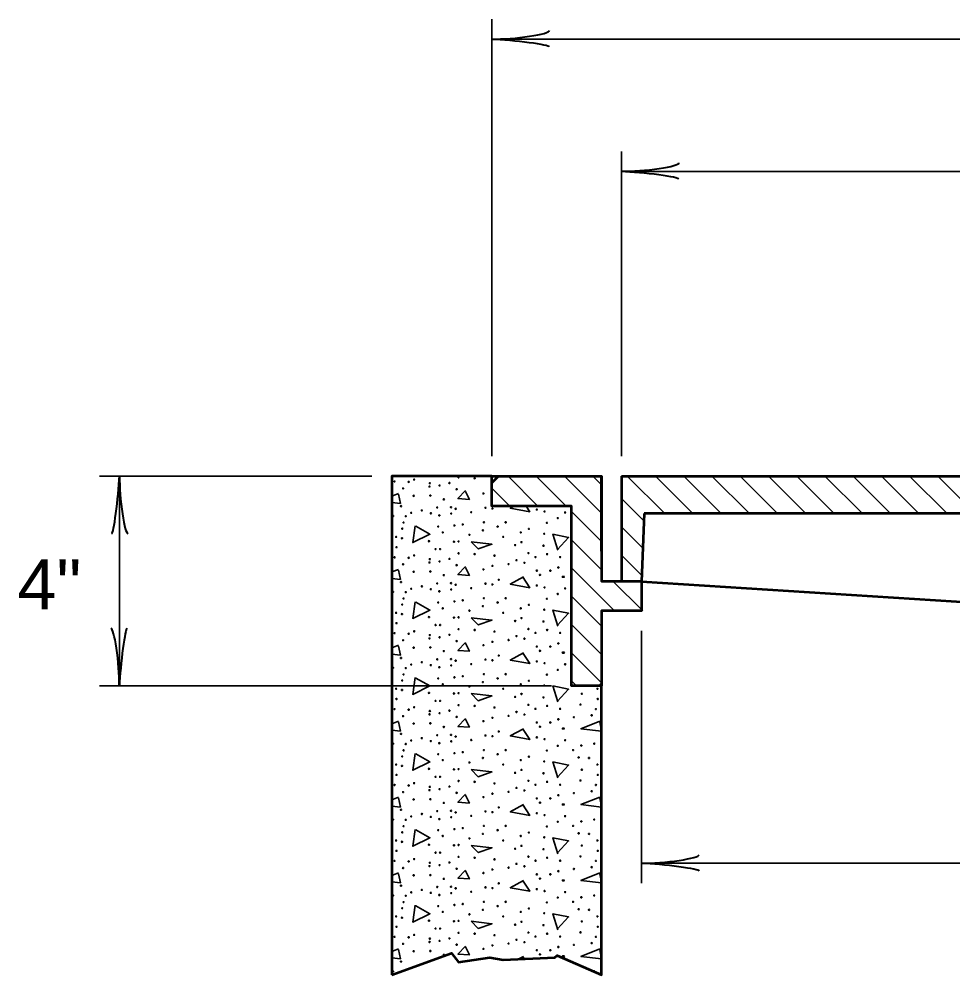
# Model space of a CAD drawing. Extents: x 788 to 1469, y -1 to 439.
# Drawn here: x 1096.98 to 1143.75, y 217.38 to 265.23 of the extents above; entities that cross this region are included whole.
import ezdxf

# ---------------------------------------------------------------- set-up
doc = ezdxf.new("R2010")
doc.units = 0
doc.layers.add('1', color=7, linetype='Continuous', lineweight=35)

msp = doc.modelspace()

# ---------------------------------------------------------------- linework, layer by layer
at = {"layer": '1'}
for p, q in [((1120.652, 243.348), (1120.652, 265.229)), ((1120.652, 264.229), (1184.152, 264.229)), ((1127.152, 243.348), (1127.152, 258.601)), ((1127.152, 257.601), (1177.652, 257.601)), ((1114.652, 242.348), (1101.003, 242.348)), ((1102.003, 242.348), (1102.003, 231.848)), ((1122.968, 240.848), (1121.468, 242.348)), ((1124.382, 240.848), (1122.882, 242.348)), ((1126.152, 240.493), (1124.297, 242.348)), ((1126.152, 241.907), (1125.711, 242.348)), ((1127.439, 242.348), (1129.314, 240.473)), ((1128.854, 242.348), (1130.729, 240.473)), ((1130.268, 242.348), (1132.143, 240.473)), ((1131.682, 242.348), (1133.557, 240.473)), ((1133.096, 242.348), (1134.971, 240.473)), ((1134.51, 242.348), (1136.385, 240.473)), ((1135.925, 242.348), (1137.8, 240.473)), ((1137.339, 242.348), (1139.214, 240.473)), ((1138.753, 242.348), (1140.628, 240.473)), ((1140.167, 242.348), (1142.042, 240.473)), ((1141.582, 242.348), (1143.457, 240.473)), ((1142.996, 242.348), (1144.871, 240.473)), ((1121.554, 240.848), (1120.652, 241.75)), ((1115.977, 241.482), (1115.652, 241.35)), ((1127.152, 241.221), (1128.267, 240.106)), ((1126.152, 239.079), (1124.652, 240.579)), ((1127.152, 239.807), (1128.215, 238.744)), ((1126.152, 237.664), (1124.652, 239.164)), ((1127.152, 238.393), (1128.163, 237.382)), ((1115.977, 237.682), (1115.652, 237.55)), ((1126.804, 235.598), (1124.652, 237.75)), ((1128.218, 235.598), (1126.718, 237.098)), ((1126.152, 234.836), (1124.652, 236.336)), ((1126.152, 233.422), (1124.652, 234.922)), ((1128.152, 234.598), (1128.152, 221.972)), ((1115.977, 233.882), (1115.652, 233.75)), ((1126.152, 232.007), (1124.652, 233.507)), ((1124.897, 231.848), (1124.652, 232.093)), ((1123.652, 231.848), (1101.003, 231.848)), ((1115.977, 230.082), (1115.652, 229.951)), ((1126.152, 229.605), (1126.057, 230.042)), ((1115.977, 226.282), (1115.652, 226.15)), ((1126.152, 225.805), (1126.057, 226.242)), ((1128.152, 222.972), (1176.652, 222.972)), ((1115.977, 222.482), (1115.652, 222.35)), ((1126.152, 222.005), (1126.057, 222.442)), ((1115.977, 218.682), (1115.652, 218.55)), ((1122.237, 218.302), (1121.983, 218.163)), ((1122.29, 218.177), (1122.197, 218.322)), ((1126.152, 218.205), (1126.057, 218.642))]:
    msp.add_line(p, q, dxfattribs=at)
at = {"layer": '1', "lineweight": 53}
for p, q in [((1120.989, 242.348), (1120.652, 242.011)), ((1126.152, 238.598), (1126.152, 242.348)), ((1127.152, 242.348), (1177.652, 242.348)), ((1127.152, 242.348), (1127.152, 237.098)), ((1128.282, 240.473), (1128.151, 237.079)), ((1151.143, 240.473), (1128.282, 240.473)), ((1128.152, 237.066), (1151.479, 235.598)), ((1126.152, 231.954), (1126.046, 231.848))]:
    msp.add_line(p, q, dxfattribs=at)
for points in [[(1120.652, 242.348), (1115.652, 242.348), (1115.652, 217.379)], [(1115.652, 217.379), (1118.642, 218.468), (1118.979, 218.018), (1120.553, 218.243), (1120.553, 218.243), (1121.227, 218.131), (1123.812, 218.243), (1123.925, 218.356), (1126.152, 217.379), (1126.152, 231.848), (1124.652, 231.848), (1124.652, 240.848), (1120.652, 240.848), (1120.652, 242.348)]]:
    msp.add_lwpolyline(points, dxfattribs=at)
msp.add_lwpolyline([(1120.652, 242.348), (1126.152, 242.348), (1126.152, 237.098), (1128.152, 237.098), (1128.152, 235.598), (1126.152, 235.598), (1126.152, 231.848), (1124.652, 231.848), (1124.652, 240.848), (1120.652, 240.848)], close=True, dxfattribs=at)
at = {"layer": '1'}
for points in [[(1115.652, 241.031), (1116.077, 240.982), (1115.977, 241.442)], [(1119.337, 241.622), (1118.957, 241.222), (1119.537, 241.182), (1119.337, 241.582)], [(1121.771, 240.848), (1121.577, 240.742), (1122.557, 240.562), (1122.373, 240.848)], [(1116.857, 239.842), (1117.557, 239.442), (1116.697, 239.022), (1116.817, 239.862)], [(1123.957, 238.642), (1123.717, 239.442), (1124.497, 239.282), (1123.937, 238.682)], [(1119.337, 237.822), (1118.957, 237.422), (1119.537, 237.382), (1119.337, 237.782)], [(1115.652, 237.231), (1116.077, 237.182), (1115.977, 237.642)], [(1122.237, 237.302), (1121.577, 236.942), (1122.557, 236.762), (1122.197, 237.322)], [(1116.857, 236.042), (1117.557, 235.642), (1116.697, 235.222), (1116.817, 236.062)], [(1123.957, 234.842), (1123.717, 235.642), (1124.497, 235.482), (1123.937, 234.882)], [(1119.337, 234.022), (1118.957, 233.622), (1119.537, 233.582), (1119.337, 233.982)], [(1115.652, 233.431), (1116.077, 233.382), (1115.977, 233.842)], [(1122.237, 233.502), (1121.577, 233.142), (1122.557, 232.962), (1122.197, 233.522)], [(1116.857, 232.242), (1117.557, 231.842), (1116.697, 231.422), (1116.817, 232.262)], [(1123.957, 231.042), (1123.717, 231.842), (1124.497, 231.682), (1123.937, 231.082)], [(1119.337, 230.222), (1118.957, 229.822), (1119.537, 229.782), (1119.337, 230.182)], [(1115.652, 229.631), (1116.077, 229.582), (1115.977, 230.042)], [(1122.237, 229.702), (1121.577, 229.342), (1122.557, 229.162), (1122.197, 229.722)], [(1126.057, 230.082), (1125.117, 229.702), (1126.152, 229.582)], [(1116.857, 228.442), (1117.557, 228.042), (1116.697, 227.622), (1116.817, 228.462)], [(1123.957, 227.242), (1123.717, 228.042), (1124.497, 227.882), (1123.937, 227.282)], [(1119.337, 226.422), (1118.957, 226.022), (1119.537, 225.982), (1119.337, 226.382)], [(1115.652, 225.831), (1116.077, 225.782), (1115.977, 226.242)], [(1122.237, 225.902), (1121.577, 225.542), (1122.557, 225.362), (1122.197, 225.922)], [(1126.057, 226.282), (1125.117, 225.902), (1126.152, 225.782)], [(1116.857, 224.642), (1117.557, 224.242), (1116.697, 223.822), (1116.817, 224.662)], [(1123.957, 223.442), (1123.717, 224.242), (1124.497, 224.082), (1123.937, 223.482)], [(1119.337, 222.622), (1118.957, 222.222), (1119.537, 222.182), (1119.337, 222.582)], [(1115.652, 222.031), (1116.077, 221.982), (1115.977, 222.442)], [(1122.237, 222.102), (1121.577, 221.742), (1122.557, 221.562), (1122.197, 222.122)], [(1126.057, 222.482), (1125.117, 222.102), (1126.152, 221.982)], [(1116.857, 220.842), (1117.557, 220.442), (1116.697, 220.022), (1116.817, 220.862)], [(1123.957, 219.642), (1123.717, 220.442), (1124.497, 220.282), (1123.937, 219.682)], [(1119.337, 218.822), (1118.957, 218.422), (1119.537, 218.382), (1119.337, 218.782)], [(1126.057, 218.682), (1125.117, 218.302), (1126.152, 218.183)], [(1115.652, 218.231), (1116.077, 218.182), (1115.977, 218.642)]]:
    msp.add_lwpolyline(points, dxfattribs=at)
for points in [[(1119.617, 239.062), (1120.657, 238.942), (1119.977, 238.702)], [(1119.617, 235.262), (1120.657, 235.142), (1119.977, 234.902)], [(1119.617, 231.462), (1120.657, 231.342), (1119.977, 231.102)], [(1119.617, 227.662), (1120.657, 227.542), (1119.977, 227.302)], [(1119.617, 223.862), (1120.657, 223.742), (1119.977, 223.502)], [(1119.617, 220.062), (1120.657, 219.942), (1119.977, 219.702)]]:
    msp.add_lwpolyline(points, close=True, dxfattribs=at)
for centre in [(1116.768, 242.178), (1118.989, 242.284), (1119.797, 242.244), (1115.787, 242.085), (1116.211, 241.732), (1116.489, 242.059), (1117.536, 241.825), (1117.55, 241.992), (1118.04, 241.878), (1118.53, 242.006), (1118.896, 241.692), (1116.741, 241.361), (1117.576, 241.374), (1118.252, 241.189), (1120.234, 241.48), (1116.105, 240.844), (1117.921, 240.778), (1118.61, 240.791), (1118.843, 240.711), (1120.34, 240.764), (1120.685, 240.725), (1122.911, 240.672), (1115.707, 240.353), (1116.344, 240.34), (1116.622, 240.512), (1117.152, 240.632), (1117.603, 240.486), (1118.027, 240.38), (1118.623, 240.473), (1119.625, 240.539), (1123.296, 240.579), (1123.958, 240.247), (1124.33, 240.526), (1116.171, 239.717), (1116.238, 240.022), (1117.974, 239.823), (1118.782, 239.876), (1119.201, 239.929), (1120.261, 240.035), (1120.95, 239.823), (1121.348, 240.035), (1122.514, 239.704), (1123.415, 240.009), (1115.866, 239.306), (1116.158, 239.24), (1118.199, 239.531), (1119.532, 239.412), (1120.208, 239.637), (1121.228, 239.306), (1122.103, 239.531), (1123.283, 239.465), (1115.88, 238.789), (1117.51, 239.094), (1118.762, 239.065), (1118.989, 239.081), (1121.825, 238.895), (1122.143, 239.041), (1123.243, 238.869), (1115.787, 238.285), (1116.768, 238.378), (1117.841, 238.696), (1118.066, 238.696), (1118.989, 238.484), (1119.797, 238.444), (1120.791, 238.365), (1122.487, 238.497), (1122.845, 238.298), (1123.428, 238.444), (1124.078, 238.298), (1116.211, 237.932), (1116.489, 238.259), (1117.536, 238.025), (1117.55, 238.192), (1118.04, 238.078), (1118.53, 238.206), (1118.896, 237.892), (1120.685, 237.853), (1121.493, 237.945), (1121.891, 238.139), (1122.289, 238.012), (1116.741, 237.561), (1117.576, 237.574), (1118.252, 237.389), (1120.234, 237.68), (1122.911, 237.614), (1123.07, 237.402), (1123.587, 237.614), (1123.985, 237.773), (1116.105, 237.044), (1117.152, 236.832), (1117.921, 236.978), (1118.61, 236.991), (1118.843, 236.911), (1120.34, 236.964), (1120.685, 236.925), (1121.003, 237.163), (1122.911, 236.872), (1124.21, 237.309), (1124.263, 237.309), (1115.707, 236.553), (1116.344, 236.54), (1116.622, 236.712), (1117.603, 236.686), (1118.027, 236.58), (1118.623, 236.673), (1119.625, 236.739), (1123.296, 236.779), (1123.958, 236.447), (1124.33, 236.726), (1116.171, 235.917), (1116.238, 236.222), (1117.974, 236.023), (1118.782, 236.076), (1119.201, 236.129), (1120.261, 236.235), (1120.95, 236.023), (1121.348, 236.235), (1122.514, 235.904), (1123.415, 236.209), (1115.866, 235.506), (1116.158, 235.44), (1118.199, 235.731), (1119.532, 235.612), (1120.208, 235.837), (1121.228, 235.506), (1122.103, 235.731), (1123.283, 235.665), (1115.88, 234.989), (1117.51, 235.294), (1118.762, 235.265), (1118.989, 235.281), (1121.825, 235.095), (1122.143, 235.241), (1123.243, 235.069), (1115.787, 234.485), (1116.489, 234.459), (1116.768, 234.578), (1117.841, 234.896), (1118.066, 234.896), (1118.989, 234.684), (1119.797, 234.644), (1120.791, 234.565), (1122.487, 234.697), (1122.845, 234.498), (1123.428, 234.644), (1124.078, 234.498), (1116.211, 234.132), (1117.536, 234.225), (1117.55, 234.392), (1118.04, 234.278), (1118.53, 234.406), (1118.896, 234.092), (1120.685, 234.053), (1121.493, 234.145), (1121.891, 234.339), (1122.289, 234.212), (1123.985, 233.973), (1116.741, 233.761), (1117.576, 233.774), (1118.252, 233.589), (1120.234, 233.88), (1122.911, 233.814), (1123.07, 233.602), (1123.587, 233.814), (1124.21, 233.509), (1124.263, 233.509), (1116.105, 233.244), (1117.152, 233.032), (1117.921, 233.178), (1118.61, 233.191), (1118.843, 233.111), (1120.34, 233.164), (1120.685, 233.125), (1121.003, 233.363), (1122.911, 233.072), (1115.707, 232.753), (1116.344, 232.74), (1116.622, 232.912), (1117.603, 232.886), (1118.027, 232.78), (1118.623, 232.873), (1119.625, 232.939), (1123.296, 232.979), (1123.958, 232.647), (1124.33, 232.926), (1116.171, 232.117), (1116.238, 232.422), (1117.974, 232.223), (1118.782, 232.276), (1119.201, 232.329), (1120.261, 232.435), (1120.95, 232.223), (1121.348, 232.435), (1122.514, 232.104), (1123.415, 232.409), (1115.866, 231.706), (1116.158, 231.64), (1118.199, 231.931), (1119.532, 231.812), (1120.208, 232.037), (1121.228, 231.706), (1122.103, 231.931), (1123.283, 231.865), (1125.946, 231.706), (1115.88, 231.189), (1117.51, 231.494), (1117.841, 231.096), (1118.066, 231.096), (1118.762, 231.465), (1118.989, 231.481), (1121.825, 231.295), (1122.143, 231.441), (1123.243, 231.269), (1125.164, 231.454), (1125.96, 231.189), (1115.787, 230.685), (1116.489, 230.659), (1116.768, 230.778), (1118.989, 230.884), (1119.797, 230.844), (1120.791, 230.765), (1122.487, 230.897), (1122.845, 230.698), (1123.428, 230.844), (1124.078, 230.698), (1125.098, 230.911), (1125.867, 230.685), (1116.211, 230.332), (1117.536, 230.425), (1117.55, 230.592), (1118.04, 230.478), (1118.53, 230.606), (1118.896, 230.292), (1120.685, 230.253), (1121.493, 230.345), (1121.891, 230.539), (1122.289, 230.412), (1123.985, 230.173), (1124.767, 230.279), (1125.655, 230.372), (1116.741, 229.961), (1117.576, 229.974), (1118.252, 229.789), (1120.234, 230.08), (1122.911, 230.014), (1123.07, 229.802), (1123.587, 230.014), (1124.21, 229.709), (1124.263, 229.709), (1116.105, 229.444), (1117.152, 229.232), (1117.921, 229.378), (1118.61, 229.391), (1118.843, 229.311), (1120.34, 229.364), (1120.685, 229.325), (1121.003, 229.563), (1122.911, 229.272), (1123.296, 229.179), (1115.707, 228.953), (1116.344, 228.94), (1116.622, 229.112), (1117.603, 229.086), (1118.027, 228.98), (1118.623, 229.073), (1119.625, 229.139), (1123.958, 228.847), (1124.33, 229.126), (1125.138, 228.861), (1125.787, 228.953), (1116.171, 228.317), (1116.238, 228.622), (1117.974, 228.423), (1118.782, 228.476), (1119.201, 228.529), (1120.208, 228.237), (1120.261, 228.635), (1120.95, 228.423), (1121.348, 228.635), (1122.514, 228.304), (1123.415, 228.609), (1124.727, 228.635), (1125.005, 228.264), (1125.522, 228.237), (1115.866, 227.906), (1116.158, 227.84), (1118.199, 228.131), (1119.532, 228.012), (1121.228, 227.906), (1122.103, 228.131), (1123.283, 228.065), (1125.946, 227.906), (1115.88, 227.389), (1117.51, 227.694), (1117.841, 227.296), (1118.066, 227.296), (1118.762, 227.665), (1118.989, 227.681), (1121.825, 227.495), (1122.143, 227.641), (1123.243, 227.469), (1125.164, 227.654), (1125.96, 227.389), (1115.787, 226.885), (1116.489, 226.859), (1116.768, 226.978), (1117.55, 226.792), (1118.53, 226.806), (1118.989, 227.084), (1119.797, 227.044), (1120.791, 226.965), (1122.487, 227.097), (1122.845, 226.898), (1123.428, 227.044), (1124.078, 226.898), (1125.098, 227.111), (1125.867, 226.885), (1116.211, 226.532), (1117.536, 226.625), (1118.04, 226.678), (1118.896, 226.492), (1120.685, 226.453), (1121.493, 226.545), (1121.891, 226.739), (1122.289, 226.612), (1123.985, 226.373), (1124.767, 226.479), (1125.655, 226.572), (1116.741, 226.161), (1117.576, 226.174), (1118.252, 225.989), (1120.234, 226.28), (1122.911, 226.214), (1123.07, 226.002), (1123.587, 226.214), (1124.21, 225.909), (1124.263, 225.909), (1116.105, 225.644), (1117.152, 225.432), (1117.921, 225.578), (1118.61, 225.591), (1118.843, 225.511), (1120.34, 225.564), (1120.685, 225.525), (1121.003, 225.763), (1122.911, 225.472), (1123.296, 225.379), (1115.707, 225.153), (1116.344, 225.14), (1116.622, 225.312), (1117.603, 225.286), (1118.027, 225.18), (1118.623, 225.273), (1119.625, 225.339), (1123.958, 225.047), (1124.33, 225.326), (1125.138, 225.061), (1125.787, 225.153), (1116.171, 224.517), (1116.238, 224.822), (1117.974, 224.623), (1118.782, 224.676), (1119.201, 224.729), (1120.208, 224.437), (1120.261, 224.835), (1120.95, 224.623), (1121.348, 224.835), (1122.514, 224.504), (1123.415, 224.809), (1124.727, 224.835), (1125.005, 224.464), (1125.522, 224.437), (1115.866, 224.106), (1116.158, 224.04), (1118.199, 224.331), (1119.532, 224.212), (1121.228, 224.106), (1122.103, 224.331), (1123.283, 224.265), (1125.946, 224.106), (1115.88, 223.589), (1117.51, 223.894), (1117.841, 223.496), (1118.066, 223.496), (1118.762, 223.865), (1118.989, 223.881), (1121.825, 223.695), (1122.143, 223.841), (1123.243, 223.669), (1125.164, 223.854), (1125.96, 223.589), (1115.787, 223.085), (1116.489, 223.059), (1116.768, 223.178), (1117.55, 222.992), (1118.53, 223.006), (1118.989, 223.284), (1119.797, 223.244), (1120.791, 223.165), (1122.487, 223.297), (1122.845, 223.098), (1123.428, 223.244), (1124.078, 223.098), (1125.098, 223.311), (1125.867, 223.085), (1116.211, 222.732), (1117.536, 222.825), (1118.04, 222.878), (1118.896, 222.692), (1120.234, 222.48), (1120.685, 222.653), (1121.493, 222.745), (1121.891, 222.939), (1122.289, 222.812), (1123.985, 222.573), (1124.767, 222.679), (1125.655, 222.772), (1116.741, 222.361), (1117.576, 222.374), (1118.252, 222.189), (1122.911, 222.414), (1123.07, 222.202), (1123.587, 222.414), (1124.21, 222.109), (1124.263, 222.109), (1116.105, 221.844), (1117.152, 221.632), (1117.921, 221.778), (1118.61, 221.791), (1118.843, 221.711), (1119.625, 221.539), (1120.34, 221.764), (1120.685, 221.725), (1121.003, 221.963), (1122.911, 221.672), (1123.296, 221.579), (1124.33, 221.526), (1115.707, 221.353), (1116.344, 221.34), (1116.622, 221.512), (1117.603, 221.486), (1118.027, 221.38), (1118.623, 221.473), (1123.958, 221.247), (1125.138, 221.261), (1125.787, 221.353), (1116.171, 220.717), (1116.238, 221.022), (1117.974, 220.823), (1118.782, 220.876), (1119.201, 220.929), (1120.208, 220.637), (1120.261, 221.035), (1120.95, 220.823), (1121.348, 221.035), (1122.514, 220.704), (1123.415, 221.009), (1124.727, 221.035), (1125.005, 220.664), (1125.522, 220.637), (1115.866, 220.306), (1116.158, 220.24), (1117.51, 220.094), (1118.199, 220.531), (1119.532, 220.412), (1121.228, 220.306), (1122.103, 220.531), (1123.283, 220.465), (1125.946, 220.306), (1115.88, 219.789), (1117.841, 219.696), (1118.066, 219.696), (1118.762, 220.065), (1118.989, 220.081), (1121.825, 219.895), (1122.143, 220.041), (1123.243, 219.869), (1125.164, 220.054), (1125.96, 219.789), (1115.787, 219.285), (1116.489, 219.259), (1116.768, 219.378), (1117.55, 219.192), (1118.53, 219.206), (1118.989, 219.484), (1119.797, 219.444), (1120.791, 219.365), (1121.891, 219.139), (1122.487, 219.497), (1122.845, 219.298), (1123.428, 219.444), (1124.078, 219.298), (1125.098, 219.511), (1125.867, 219.285), (1116.211, 218.932), (1117.536, 219.025), (1118.04, 219.078), (1118.896, 218.892), (1120.234, 218.68), (1120.685, 218.853), (1121.493, 218.945), (1122.289, 219.012), (1123.985, 218.773), (1124.767, 218.879), (1125.655, 218.972), (1116.741, 218.561), (1117.576, 218.574), (1118.252, 218.389), (1122.911, 218.614), (1123.07, 218.402), (1123.587, 218.614), (1124.21, 218.309), (1124.263, 218.309), (1116.105, 218.044), (1115.707, 217.553)]:
    msp.add_circle(centre, 0.0265, dxfattribs=at)
for centre, start, end in [((1116.622, 217.712), 65.5499, 154.4586), ((1121.003, 218.163), 0.7757, 160.2951), ((1125.787, 217.553), 306.7351, 185.9276)]:
    msp.add_arc(centre, 0.0265, start, end, dxfattribs=at)
at = {"layer": '1', "lineweight": 40}
for centre, major_axis, ratio, start_param, end_param in [((1121.752, 264.498), (-1.786, -0.156), 0.122415, 0.896353, 3.141593), ((1121.781, 264.01), (-1.756, 0.176), 0.07063, 3.140715, 5.41811), ((1128.243, 257.878), (-1.786, -0.156), 0.122415, 0.896353, 3.141593), ((1128.272, 257.39), (-1.756, 0.176), 0.07063, 3.140715, 5.41811), ((1101.792, 241.227), (0.176, 1.756), 0.07063, 3.140715, 5.41811), ((1101.792, 241.227), (0.176, 1.756), 0.07063, 3.140715, 5.41811), ((1102.28, 241.257), (-0.156, 1.786), 0.122415, 0.896353, 3.141593), ((1102.28, 241.257), (-0.156, 1.786), 0.122415, 0.896353, 3.141593), ((1101.727, 232.939), (0.156, -1.786), 0.122415, 0.896353, 3.141593), ((1102.215, 232.969), (-0.176, -1.756), 0.07063, 3.140715, 5.41811), ((1129.252, 223.241), (-1.786, -0.156), 0.122415, 0.896353, 3.141593), ((1129.281, 222.753), (-1.756, 0.176), 0.07063, 3.140715, 5.41811)]:
    msp.add_ellipse(centre, major_axis=major_axis, ratio=ratio, start_param=start_param, end_param=end_param, dxfattribs=at)

# ---------------------------------------------------------------- texts
at = {"layer": '1', "width": 1.05}
msp.add_text('4"', height=2.5, dxfattribs=at).set_placement((1096.9, 235.676))

doc.saveas('drawing.dxf')
